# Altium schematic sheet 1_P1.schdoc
size 429 x 307 mm; Symbol: Sheet-Symbol_A5; Device: Sheet-Symbol_A5; Company: 嘉立创EDA; Version: V1.0; Page Size: A3; @Project Name: BT-AI_PlanetaryCore-V1.00; @Page Count: 1; @Update Date: 2025-09-01; @Create Date: 2025-08-25; @Schematic Name: Schematic1; @Page No: 1; @Page Name: P1; Title Block Position: 3; Width: 1655; Height: 1170; Region Start: 1; X Region Count: 6; Y Region Count: 4; Blade Width: 10; @Board Name: Board1; @Create Time: 15:47:36; @Update Time: 15:24:10
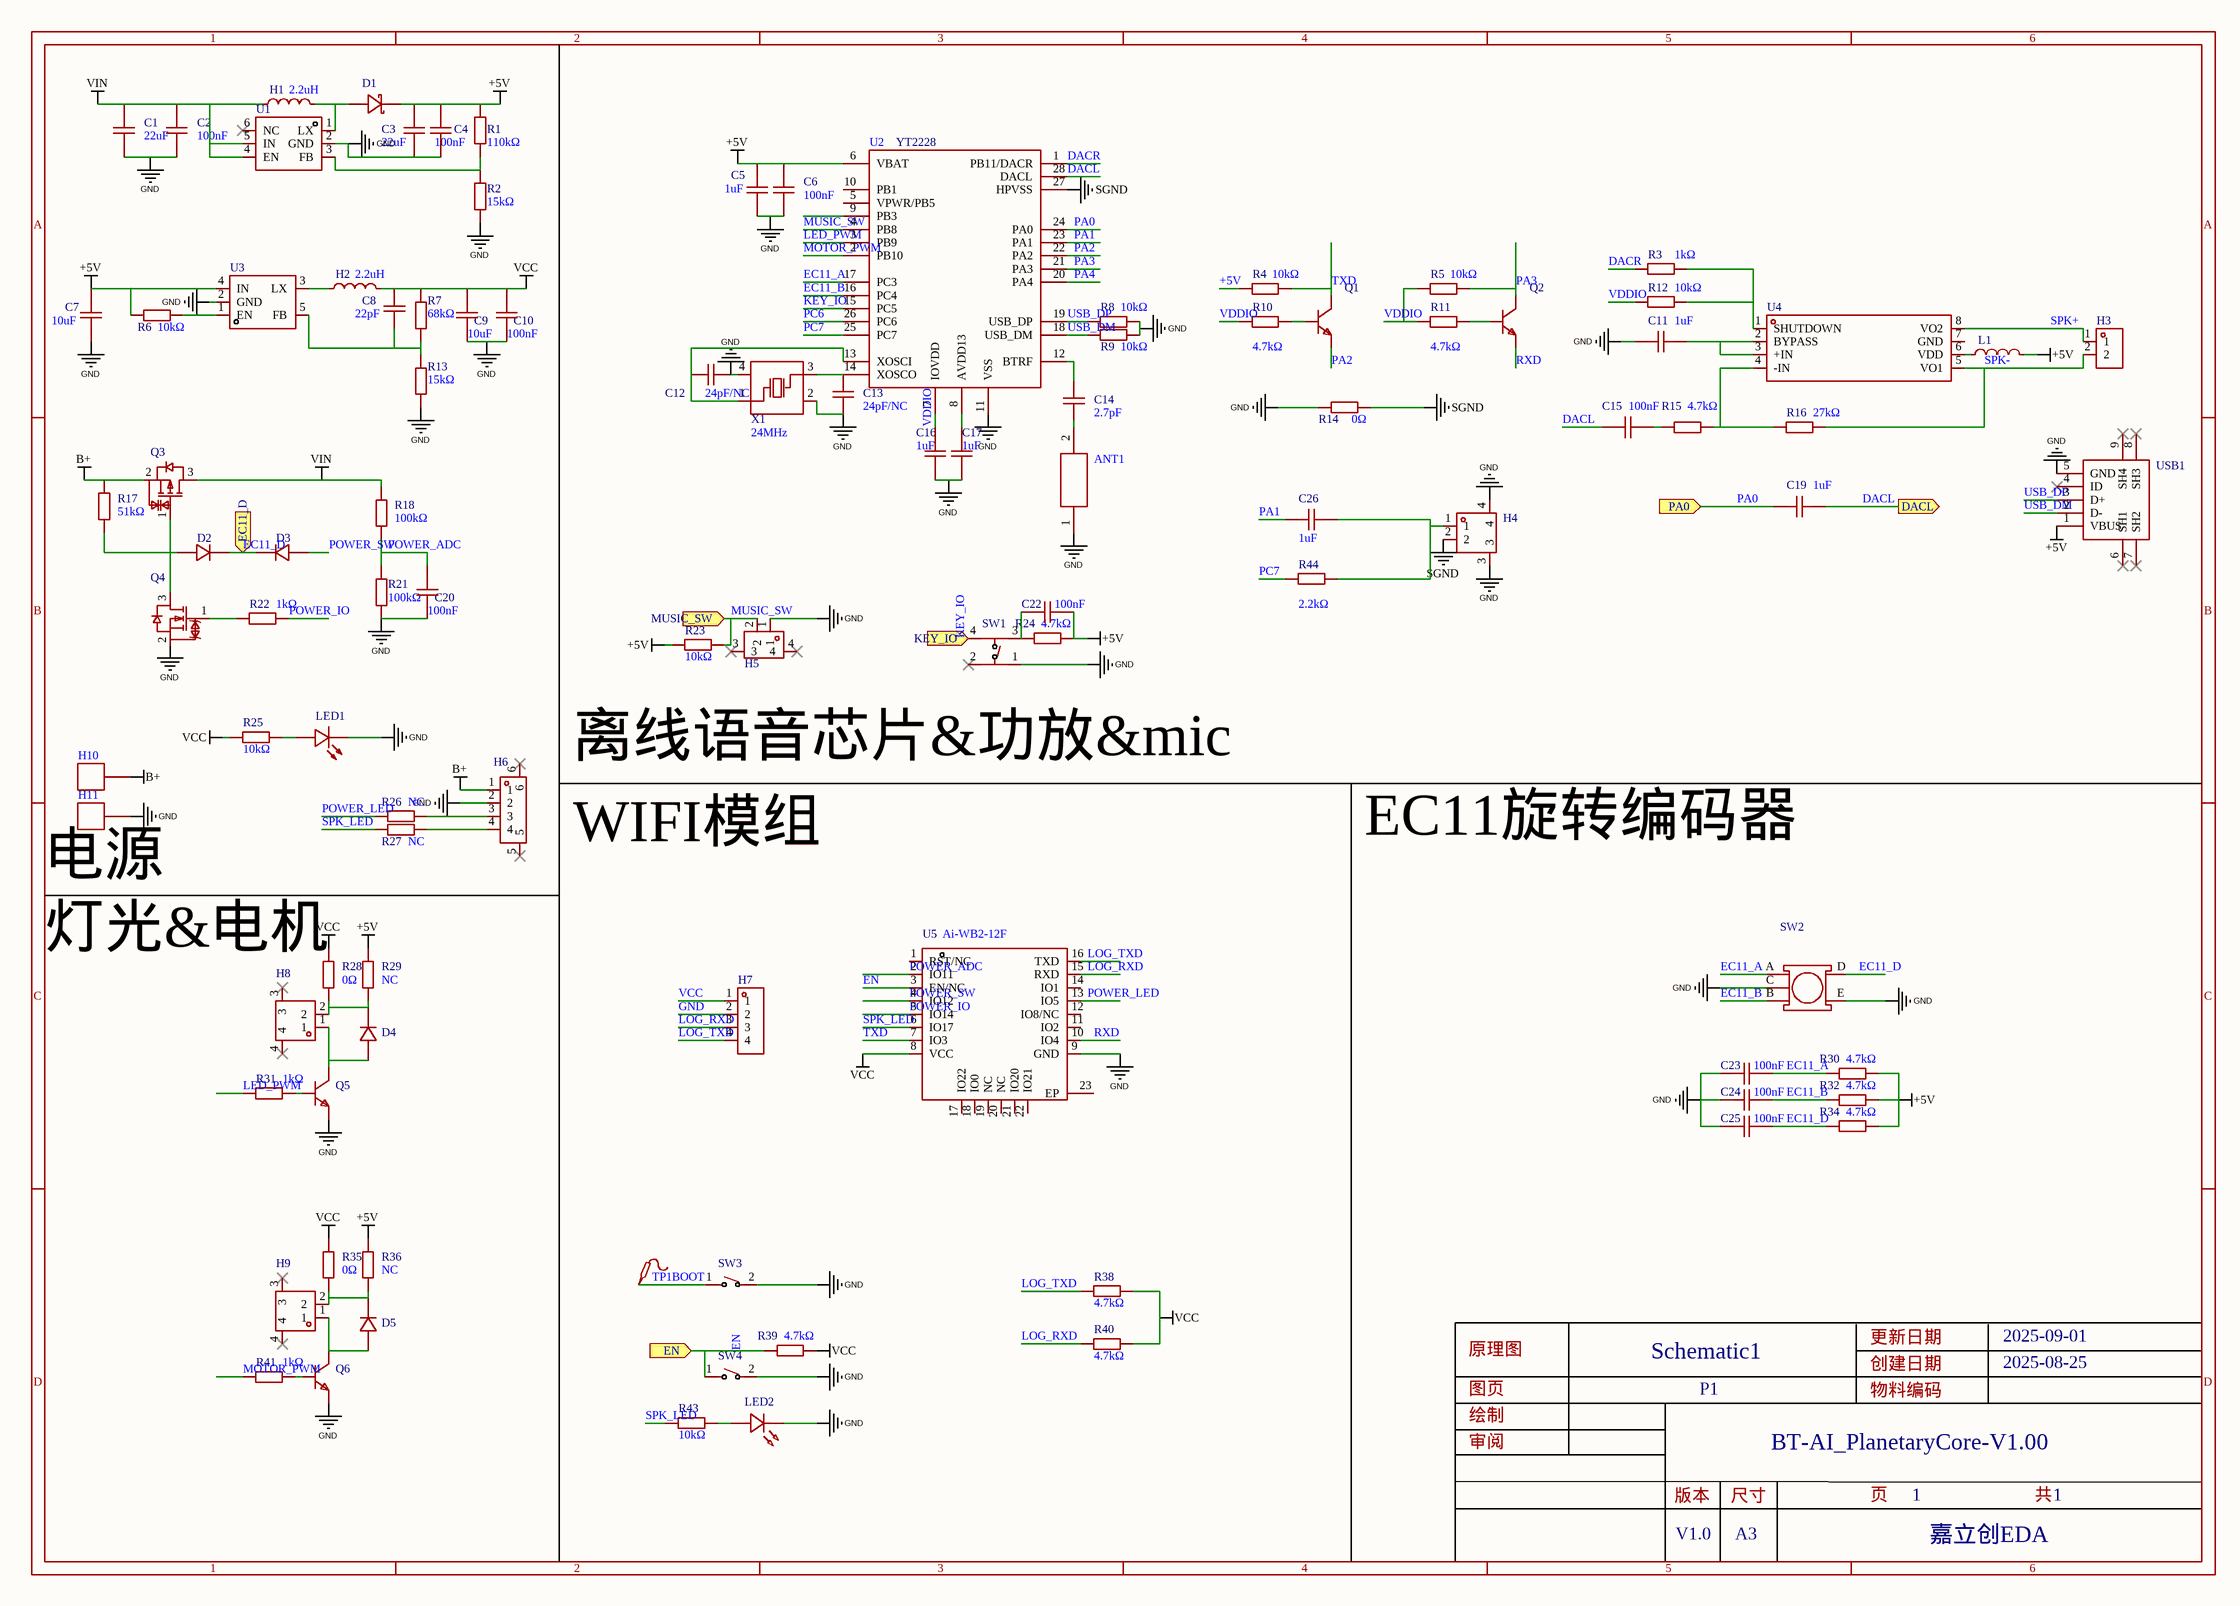
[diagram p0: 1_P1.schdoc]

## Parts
ANT1  (no value)  [板载天线]
C1  22uF  [C0603]
C2  100nF  [C0603]
C3  22uF  [C0603]
C4  100nF  [C0603]
C5  1uF  [C0603]
C6  100nF  [C0603]
C7  10uF  [C0603]
C8  22pF  [C0603]
C9  10uF  [C0603]
C10  100nF  [C0603]
C11  1uF  [C0603]
C12  24pF/NC  [C0603]
C13  24pF/NC  [C0603]
C14  2.7pF  [C0402]
C15  100nF  [C0603]
C16  1uF  [C0603]
C17  1uF  [C0603]
C19  1uF  [C0603]
C20  100nF  [C0603]
C22  100nF  [C0603]
C23  100nF  [C0603]
C24  100nF  [C0603]
C25  100nF  [C0603]
C26  1uF  [C0603]
D1  SS14  [SOD-123FL_L2.8-W1.8-LS3.7-RD]  (value not drawn)
D2  1N4148WS  [SOD-323_L1.8-W1.3-LS2.5-RD]  (value not drawn)
D3  1N4148WS  [SOD-323_L1.8-W1.3-LS2.5-RD]  (value not drawn)
D4  SM4007PL  [SOD-123F_L2.8-W1.8-LS3.7-RD]  (value not drawn)
D5  SM4007PL  [SOD-123F_L2.8-W1.8-LS3.7-RD]  (value not drawn)
H1  2.2uH  [IND-SMD_L2.0-W1.6-B]
H2  2.2uH  [IND-SMD_L2.0-W1.6-B]
H3  JS20T-S02PHA-00  [CONN-TH_2P-P2.00_JS20T-S02PHA-00]  (value not drawn)
H4  1.25-2P  [CONN-SMD_1.25-2P]  (value not drawn)
H5  ZX-ZH1.5-2PLT  [CONN-SMD_2P-P1.50_ZX-ZH1.5-2PLT]  (value not drawn)
H6  ZX-ZH1.5-4PLT  [CONN-SMD_4P-P1.50_ZX-ZH1.5-4PLT]  (value not drawn)
H7  PZ254V-11-04P  [HDR-TH_4P-P2.54-V-M]  (value not drawn)
H8  1.25-2P  [CONN-SMD_1.25-2P]  (value not drawn)
H9  1.25-2P  [CONN-SMD_1.25-2P]  (value not drawn)
H10  (no value)  [标志点]
H11  (no value)  [标志点]
L1  PZ1608D600-2R0TF  [L0603]  (value not drawn)
LED1  KT-0603R  [LED0603-RD]  (value not drawn)
LED2  XL-1608UBC-04  [LED0603-RD_BLUE]  (value not drawn)
Q1  S8050  [SOT-23-3_L3.0-W1.7-P0.95-LS2.9-BR]  (value not drawn)
Q2  S8050  [SOT-23-3_L3.0-W1.7-P0.95-LS2.9-BR]  (value not drawn)
Q3  AO3415A  [SOT-23-3_L3.0-W1.7-P0.95-LS2.9-BR]  (value not drawn)
Q4  AO3416A  [SOT-23-3_L3.0-W1.7-P0.95-LS2.9-BR]  (value not drawn)
Q5  S8050 J3Y(RANGE:200-350)  [SOT-23-3_L3.0-W1.7-P0.95-LS2.9-BR]  (value not drawn)
Q6  S8050 J3Y(RANGE:200-350)  [SOT-23-3_L3.0-W1.7-P0.95-LS2.9-BR]  (value not drawn)
R1  110kΩ  [R0603]
R2  15kΩ  [R0603]
R3  1kΩ  [R0603]
R4  10kΩ  [R0603]
R5  10kΩ  [R0603]
R6  10kΩ  [R0603]
R7  68kΩ  [R0603]
R8  10kΩ  [R0603]
R9  10kΩ  [R0603]
R10  4.7kΩ  [R0603]
R11  4.7kΩ  [R0603]
R12  10kΩ  [R0603]
R13  15kΩ  [R0603]
R14  0Ω  [R0603]
R15  4.7kΩ  [R0603]
R16  27kΩ  [R0603]
R17  51kΩ  [R0603]
R18  100kΩ  [R0603]
R21  100kΩ  [R0603]
R22  1kΩ  [R0603]
R23  10kΩ  [R0603]
R24  4.7kΩ  [R0603]
R25  10kΩ  [R0603]
R26  NC  [R0603]
R27  NC  [R0603]
R28  0Ω  [R0603]
R29  NC  [R0603]
R30  4.7kΩ  [R0603]
R31  1kΩ  [R0603]
R32  4.7kΩ  [R0603]
R34  4.7kΩ  [R0603]
R35  0Ω  [R0603]
R36  NC  [R0603]
R38  4.7kΩ  [R0603]
R39  4.7kΩ  [R0603]
R40  4.7kΩ  [R0603]
R41  1kΩ  [R0603]
R43  10kΩ  [R0603]
R44  2.2kΩ  [R0603]
SW1  YZA-056-5.0  [SW-SMD_4P-L4.5-W4.5-P3.00-LS6.8]  (value not drawn)
SW2  EC11J1525402  [EC11]  (value not drawn)
SW3  TSB008A2530A  [SW-SMD_L6.0-W3.5-LS8.0]  (value not drawn)
SW4  TSB008A2530A  [SW-SMD_L6.0-W3.5-LS8.0]  (value not drawn)
TP1  (no value)  [Test-Point-0.5mm]
U1  STI3508C  [SOT-23-6_L2.9-W1.6-P0.95-LS2.8-BR]  (value not drawn)
U2  (no value)  [QSOP-28_L9.9-W3.9-P0.64-LS6.0-BL]
U3  RT8059GJ5-TP  [SOT-23-5_L2.9-W1.6-P0.95-LS2.8-BR_1]  (value not drawn)
U4  8002A  [SOP-8_L4.9-W3.9-P1.27-LS6.0-BL]  (value not drawn)
U5  2.4GHz  [COMM-SMD_22P-L24.0-W16.0-P2.00_ZIGBEE]  (value not drawn)
USB1  MicroQTJ  [MICRO-USB-SMD_MICROQTJ-5P]  (value not drawn)
X1  24MHz  [CRYSTAL-SMD_4P-L3.2-W2.5-BL]

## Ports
DACL (out), EC11_D (in), EN (in), KEY_IO (in), MUSIC_SW (in), PA0 (in)

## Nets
+5V: C3.2 C4.2 C5.2 C6.2 C7.1 C22.1 D1.1(A) L1.2 R1.2 R4.1 R6.1 R23.2 R24.2 R29.2 R30.2 R32.2 R34.2 R36.2 U2.6(VBAT) U3.4(IN) USB1.1(VBUS)
B+: H6.1 H10.1 Q3.2(S) R17.2
GND: ANT1.1 C1.1 C2.1 C3.1 C4.1 C5.1 C6.1 C7.2 C9.1 C10.1 C11.1 C12.1 C13.2 C16.1 C17.1 C20.1 C23.2 C24.2 C25.2 H4.3 H4.4 H5.1 H6.2 H7.2 H11.1 LED1.1(K) LED2.1(K) Q4.2(S) Q5.2(E) Q6.2(E) R2.2 R8.2 R9.2 R13.1 R14.1 R21.1 SW1.1 SW2.C SW2.E SW3.2 SW4.2 U1.2(GND) U2.11(VSS) U3.2(GND) U5.9(GND) USB1.5(GND) X1.2(GND) X1.4(GND)
SGND: H4.2 R14.2 U2.27(HPVSS)
VCC: C8.2 C9.2 C10.2 H2.2 H7.1 R7.2 R25.2 R28.2 R35.2 R38.2 R39.2 R40.2 U5.8(VCC)
VIN: C1.2 C2.2 H1.1 Q3.3(D) R18.2 U1.4(EN) U1.5(IN)
BOOT: SW3.1 TP1.1
DACL: C15.2 C19.2 U2.28(DACL) ; port DACL
DACR: R3.1 U2.1(PB11/DACR)
EC11_A: C23.1 R30.1 SW2.A U2.17(PC3)
EC11_B: C24.1 R32.1 SW2.B U2.16(PC4)
EC11_D: C25.1 D2.1(K) D3.1(K) R34.1 SW2.D ; port EC11_D
EN: R39.1 SW4.1 U5.3(EN/NC) ; port EN
KEY_IO: SW1.4 U2.15(PC5) ; port KEY_IO
LED_PWM: R31.1 U2.3(PB9)
LOG_RXD: H7.3 R40.1 U5.15(RXD)
LOG_TXD: H7.4 R38.1 U5.16(TXD)
MOTOR_PWM: R41.1 U2.2(PB10)
MUSIC_SW: H5.2 R23.1 U2.4(PB8) ; port MUSIC_SW
PA0: C19.1 U2.24(PA0) ; port PA0
PA1: C26.2 U2.23(PA1)
PA2: Q1.2(E) U2.22(PA2)
PA3: Q2.3(C) R5.2 U2.21(PA3)
PA4: U2.20(PA4)
PC6: U2.26(PC6)
PC7: R44.1 U2.25(PC7)
POWER_ADC: C20.2 R18.1 R21.2 U5.2(IO11)
POWER_IO: R22.2 U5.5(IO14)
POWER_LED: R26.2 U5.13(IO5)
POWER_SW: D3.2(A) U5.4(IO12)
RXD: Q2.2(E) U5.10(IO4)
SPK+: H3.1 U4.8(VO2)
SPK-: H3.2 R16.2 U4.5(VO1)
SPK_LED: R27.2 R43.2 U5.6(IO17)
TXD: Q1.3(C) R4.2 U5.7(IO3)
USB_DM: R9.1 U2.18(USB_DM) USB1.2(D-)
USB_DP: R8.1 U2.19(USB_DP) USB1.3(D+)
VDDIO: C16.2 R5.1 R10.1 R11.1 R12.1 U2.7(IOVDD)
NetANT1_2: ANT1.2 C14.1
NetC8_1: C8.1 R7.1 R13.2 U3.5(FB)
NetC11_2: C11.2 U4.2(BYPASS) U4.3(+IN)
NetC12_2: C12.2 U2.13(XOSCI) X1.1(OSC1)
NetC13_1: C13.1 U2.14(XOSCO) X1.3(OSC2)
NetC14_2: C14.2 U2.12(BTRF)
NetC15_1: C15.1 R15.1
NetC17_2: C17.2 U2.8(AVDD13)
NetC22_2: C22.2 R24.1 SW1.3
NetC26_1: C26.1 H4.1 R44.2
NetD1_2: D1.2(K) H1.2 U1.1(LX)
NetD2_2: D2.2(A) Q3.1(G) Q4.3(D) R17.1
NetD4_1: D4.1(C) H8.2 R28.1 R29.1
NetD4_2: D4.2(A) H8.1 Q5.3(C)
NetD5_1: D5.1(C) H9.2 R35.1 R36.1
NetD5_2: D5.2(A) H9.1 Q6.3(C)
NetH2_1: H2.1 U3.3(LX)
NetH6_3: H6.3 R26.1
NetH6_4: H6.4 R27.1
NetL1_1: L1.1 U4.6(VDD)
NetLED1_2: LED1.2(A) R25.1
NetLED2_2: LED2.2(A) R43.1
NetQ1_1: Q1.1(B) R10.2
NetQ2_1: Q2.1(B) R11.2
NetQ4_1: Q4.1(G) R22.1
NetQ5_1: Q5.1(B) R31.2
NetQ6_1: Q6.1(B) R41.2
NetR1_1: R1.1 R2.1 U1.3(FB)
NetR3_2: R3.2 R12.2 U4.1(SHUTDOWN)
NetR6_2: R6.2 U3.1(EN)
NetR15_2: R15.2 R16.1 U4.4(-IN)

Not connected (* = marked no-connect by the designer): H5 3* 4*; H6 5* 6*; H8 3* 4*; H9 3* 4*; SW1 2*; U1 6(NC)*; U2 5(VPWR/PB5) 9(PB3) 10(PB1); U4 7(GND); U5 1(RST/NC) 11(IO2) 12(IO8/NC) 14(IO1) 17(IO22) 18(IO0) 19(NC) 20(NC) 21(IO20) 22(IO21) 23(EP); USB1 4(ID)* 6(SH1)* 7(SH2)* 8(SH3)* 9(SH4)*

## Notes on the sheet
- 离线语音芯片&功放&mic
- (near H11) 电源
- WIFI模组
- EC11旋转编码器
- 灯光&电机

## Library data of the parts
ANT1 = IFA_RF: Add into BOM: yes
C1 C3 = CL10A226MQ8NRNC: Manufacturer: SAMSUNG(三星); Add into BOM: yes; Tolerance: ±20%; Voltage Rating: 6.3V; Temperature Coefficient: X5R
C2 C4 C6 C10 C15 C20 C22-C25 = CC0603KRX7R9BB104: Manufacturer: YAGEO(国巨); Add into BOM: yes; Tolerance: ±10%; Voltage Rating: 50V; Temperature Coefficient: X7R
C5 C11 C16 C17 C19 C26 = CL10A105KB8NNNC: Manufacturer: SAMSUNG(三星); Add into BOM: yes; Tolerance: ±10%; Voltage Rating: 50V; Temperature Coefficient: X5R
C7 C9 = CL10A106KP8NNNC: Manufacturer: SAMSUNG(三星); Add into BOM: yes; Tolerance: ±10%; Voltage Rating: 10V; Temperature Coefficient: X5R
C8 = CL10C220JB8NNNC: Manufacturer: SAMSUNG(三星); Add into BOM: yes; Tolerance: ±5%; Voltage Rating: 50V; Temperature Coefficient: C0G
C12 C13 = 0603CG240J500NT: Manufacturer: FH(风华); Add into BOM: yes; Tolerance: ±5%; Voltage Rating: 50V; Temperature Coefficient: C0G
C14 = 0402CG2R7C500NT: Manufacturer: FH(风华); Add into BOM: yes; Voltage Rated: 50V; Temperature Coefficient: C0G
D1 = SS14_C2909920: Manufacturer: KUU; Add into BOM: yes; Diode Configuration: 独立式; Voltage - Forward(Vf@If): 550mV@1A; Voltage - DC Reverse(Vr): 40V; Current - Rectified: 1A; Reverse Leakage Current (Ir): 500uA@40V
D2 D3 = 1N4148WS_C2128: Manufacturer: CJ(江苏长电/长晶); Symbol: 1N4148WS T4; Add into BOM: yes; Diode Configuration: 独立式; Voltage - Forward(Vf@If): 1.25V@150mA; Voltage - DC Reverse(Vr): 100V; Current - Rectified: 150mA; Pd - Power Dissipation: 200mW; Reverse Leakage Current (Ir): 1uA@75V; Reverse Recovery Time (trr): 4ns; Non-Repetitive Peak Forward Surge Current: 2A
D4 D5 = SM4007PL_C64898: Manufacturer: MDD(辰达半导体); Add into BOM: yes; Diode Configuration: 独立式; Voltage - Forward(Vf@If): 1.1V@1A; Voltage - DC Reverse(Vr): 1kV; Current - Rectified: 1A; Reverse Leakage Current (Ir): 10uA@1kV; Non-Repetitive Peak Forward Surge Current: 25A; Operating Junction Temperature Range: -55℃~+150℃
H1 H2 = FTC201610S2R2MBCA: Manufacturer: cjiang(长江微电); Add into BOM: yes; Tolerance: ±20%; Current Rating: 2.5A; Current - Saturation(Isat): 3A; DC Resistance(DCR): 120mΩ
H3 = JS20T-S02PHA-00: Manufacturer: JS(钜硕电子); Add into BOM: yes; Pins Structure: 1x2P; Pitch: 2mm; Reference Series: PH; Number of PINs Per Row: 2
H4 H8 H9 = 1.25-2P: Manufacturer: SHOU HAN(首韩); Add into BOM: yes; Pins Structure: 1x2P; Pitch: 1.25mm; Reference Series: PicoBlade(MX 1.25); Number of PINs Per Row: 2; Current Rating: 1A; Voltage Rating: 125V; Plastic Material: LCP; Flame Retardant Rating: UL94V-0
H5 = ZX-ZH1.5-2PLT: Manufacturer: Megastar(兆星); Add into BOM: yes; Pins Structure: 1x2P; Pitch: 1.5mm; Reference Series: ZH; Number of PINs Per Row: 2; Voltage Rating: 250V; Plastic Material: LCP; Supplementary Features: 辅助焊脚; Z-Height of the Board: 5.1mm; X-Length of Bottom Edge on Board (Spacing Line): 6mm; Y-Width of Bottom Edge on Board: 5.2mm
H6 = ZX-ZH1.5-4PLT: Manufacturer: Megastar(兆星); Add into BOM: yes; Pins Structure: 1x4P; Pitch: 1.5mm; Reference Series: ZH; Number of PINs Per Row: 4; Voltage Rating: 250V; Plastic Material: LCP; Supplementary Features: 辅助焊脚; Z-Height of the Board: 5.1mm; X-Length of Bottom Edge on Board (Spacing Line): 9mm; Y-Width of Bottom Edge on Board: 5.2mm
H7 = PZ254V-11-04P: Manufacturer: XFCN(兴飞); Symbol: PZ254V-11-04P_C2691448; Add into BOM: yes; Pin Structure: 1x4P; Pitch: 2.54mm; Circluar Pins/Square Pins: 方针; Current Rating: 3A; Voltage Rating (Max): 250V
H10 H11 = 标志位: Add into BOM: yes
L1 = PZ1608D600-2R0TF: Manufacturer: Sunlord(顺络); Add into BOM: yes; Impedance @ Frequency: 60Ω@100MHz; Tolerance: ±25%; DC Resistance: 80mΩ; Current Rating: 2A; Circuits: 1
LED1 = KT-0603R: Manufacturer: KENTO; Add into BOM: yes; Emitted Color: 红色
LED2 = XL-1608UBC-04: Manufacturer: XINGLIGHT(成兴光); Add into BOM: yes; Illumination Color: 蓝色; Voltage - Forward(Vf): 3.3V; Power(Watts): 70mW; Forward Current: 20mA; Wavelength - Dominant: 455nm~475nm; Peak Wavelength: 470nm; Lens Color: 无色透明透镜; Luminous Intensity: 300mcd; Viewing Angle: 120°
Q1 Q2 = S8050_C364312: Manufacturer: MDD(辰达半导体); Symbol: S8050-J3Y; Add into BOM: yes; type: NPN; Current - Collector(Ic): 500mA; Collector - Emitter Voltage VCEO: 25V; Pd - Power Dissipation: 300mW; Transition frequency(fT): 150MHz; Current - Collector Cutoff: 100nA; Vce Saturation(VCE(sat)): 600mV@500mA,50mA; Emitter-Base Voltage(Vebo): 5V
Q3 = AO3415A_C347479: Manufacturer: UMW(友台半导体); Add into BOM: yes; Number: 1个P沟道; Drain to Source Voltage: 20V; Current - Continuous Drain(Id): 4A; RDS(on): 36mΩ@4.5V；60mΩ@2.5V; Pd - Power Dissipation: 350mW; Gate Threshold Voltage (Vgs(th)): 560mV@250uA; Gate Charge(Qg): 17.2nC@4.5V; Input Capacitance(Ciss): 1.45nF; Reverse Transfer Capacitance (Crss@Vds): 160pF; Type: N沟道; Output Capacitance(Coss): 205pF
Q4 = AO3416A: Manufacturer: UMW(友台半导体); Add into BOM: yes; Number: 1个N沟道; Drain to Source Voltage: 20V; Current - Continuous Drain(Id): 6A; RDS(on): 25mΩ@4.5V; Pd - Power Dissipation: 1.4W; Gate Threshold Voltage (Vgs(th)): 1.1V@250uA; Gate Charge(Qg): 10nC@4.5V; Input Capacitance(Ciss): 1.295nF; Reverse Transfer Capacitance (Crss@Vds): 87pF; Output Capacitance(Coss): 160pF
Q5 Q6 = S8050 J3Y(RANGE:200-350): Manufacturer: CJ(江苏长电/长晶); Symbol: S8050_C2146; Add into BOM: yes; type: NPN; Current - Collector(Ic): 500mA; Collector - Emitter Voltage VCEO: 25V; Pd - Power Dissipation: 300mW; DC Current Gain: 200@500mA,1V; Transition frequency(fT): 150MHz; Current - Collector Cutoff: 100nA; Vce Saturation(VCE(sat)): 600mV@500mA,50mA; Emitter-Base Voltage(Vebo): 5V; Number: 1个NPN
R1 = 0603WAF1103T5E: Manufacturer: UNI-ROYAL(厚声); Add into BOM: yes; Tolerance: ±1%; Power(Watts): 100mW; Voltage-Supply(Max): 75V; Temperature Coefficient: ±100ppm/℃
R2 R13 = 0603WAF1502T5E: Manufacturer: UNI-ROYAL(厚声); Add into BOM: yes; Tolerance: ±1%; Power(Watts): 100mW; Voltage-Supply(Max): 75V; Temperature Coefficient: ±100ppm/℃
R3 R22 R31 R41 = 0603WAF1001T5E: Manufacturer: UNI-ROYAL(厚声); Add into BOM: yes; Tolerance: ±1%; Power(Watts): 100mW; Overload Voltage (Max): 75V; Temperature Coefficient: ±100ppm/℃
R4-R6 R8 R9 R12 R23 R25 R43 = 0603WAF1002T5E: Manufacturer: UNI-ROYAL(厚声); Add into BOM: yes; Tolerance: ±1%; Power(Watts): 100mW; Voltage-Supply(Max): 75V; Temperature Coefficient: ±100ppm/℃
R7 = 0603WAF6802T5E: Manufacturer: UNI-ROYAL(厚声); Add into BOM: yes; Tolerance: ±1%; Power(Watts): 100mW; Voltage-Supply(Max): 75V; Temperature Coefficient: ±100ppm/℃
R10 R11 R15 R24 R30 R32 R34 R38-R40 = 0603WAF4701T5E: Manufacturer: UNI-ROYAL(厚声); Add into BOM: yes; Tolerance: ±1%; Power(Watts): 100mW; Voltage-Supply(Max): 75V; Temperature Coefficient: ±100ppm/℃
R14 R26-R29 R35 R36 = 0603WAF0000T5E: Manufacturer: UNI-ROYAL(厚声); Add into BOM: yes; Tolerance: ±1%; Power(Watts): 100mW; Voltage-Supply(Max): 75V
R16 = 0603WAF2702T5E: Manufacturer: UNI-ROYAL(厚声); Add into BOM: yes; Tolerance: ±1%; Power(Watts): 100mW; Voltage-Supply(Max): 75V; Temperature Coefficient: ±100ppm/℃
R17 = 0603WAF5102T5E: Manufacturer: UNI-ROYAL(厚声); Add into BOM: yes; Tolerance: ±1%; Power(Watts): 100mW; Voltage-Supply(Max): 75V; Temperature Coefficient: ±100ppm/℃
R18 R21 = 0603WAF1003T5E: Manufacturer: UNI-ROYAL(厚声); Add into BOM: yes; Tolerance: ±1%; Power(Watts): 100mW; Voltage-Supply(Max): 75V; Temperature Coefficient: ±100ppm/℃
R44 = 0603WAF2201T5E: Manufacturer: UNI-ROYAL(厚声); Add into BOM: yes; Tolerance: ±1%; Power(Watts): 100mW; Overload Voltage (Max): 75V; Temperature Coefficient: ±100ppm/℃
SW1 = YZA-056-5.0: Manufacturer: YIZHI(逸致); Add into BOM: yes; PressForce: 260gf; Switch Size: 4.5*4.5*5.0MM; Installation Method: 正按; RatedCurrent: 50mA; ButtonShape: 矩形按钮; Circuit: 单刀单掷
SW2 = EC11J1525402: Manufacturer: ALPSALPINE(阿尔卑斯阿尔派); Add into BOM: yes
SW3 SW4 = TSB008A2530A: Manufacturer: BZCN(博众电气); Add into BOM: yes; Actuator Style: 矩形按钮; Operating Force: 3N; Switch Height: 2.5mm; Contact Current: 50mA; Voltage Rating: 12V; Actuator/Cap Color: 白色
TP1 = Test-Point: Add into BOM: yes
U1 = STI3508C: Manufacturer: TMI(拓尔微); Add into BOM: yes; Function: 升压型; Output Type: 可调; Voltage - Supply: 2.5V~5.5V; Frequency - Switching: 1.2MHz; Synchronous Rectifier: 否; Number of Outputs: 1; Topology: 升压式; Quiescent Current: 30uA; Switch tube (built-in/external): 内置
U2 = YT2228: Add into BOM: yes
U3 = RT8059GJ5-TP: Manufacturer: TECH PUBLIC(台舟); Add into BOM: yes; Function: 降压型; Output Type: 可调; Voltage - Supply: 2.5V~5.5V; Output Current: 1A; Frequency - Switching: 1.5MHz; Synchronous Rectifier: 否; Number of Outputs: 1; Topology: 降压式; Quiescent Current: 150uA; Switch tube (built-in/external): 内置
U4 = 8002A: Manufacturer: IDCHIP(英锐芯); Add into BOM: yes; Speaker Channels: 单声道; Output Power: 3Wx1@4Ω; Voltage - Supply: 2.2V~5.5V
U5 = Ai-WB2-12F: Manufacturer: Ai-Thinker(安信可); Utilized IC / Part: BL602芯片; Add into BOM: yes; Wireless Standard: 802.11b/g/n；BLE5.0; Interface Type: I2C；GPIO；UART；PWM；SPI；ADC; Antenna Type: 板载PCB天线; Output Power: 16dBm; Voltage - Supply: 3.3V; Receive  Current: 65mA; Send  Current: 260mA; Sensitivity: -98dBm
USB1 = MicroQTJ: Manufacturer: SHOU HAN(首韩); Add into BOM: yes; Connector Type: Micro-B; Gender: 母; Number of Contacts: 5P; Number of Ports: 1; Connect-Disconnect Life: 3千次; Core Colour: 黑色
X1 = X322524MOB4SI: Manufacturer: YXC(扬兴晶振); Add into BOM: yes; Normal temperature Frequency Tolerance: ±10ppm; Load Capacitance: 12pF; Frequency Stability: ±20ppm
